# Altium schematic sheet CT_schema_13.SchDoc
size 387 x 385 mm
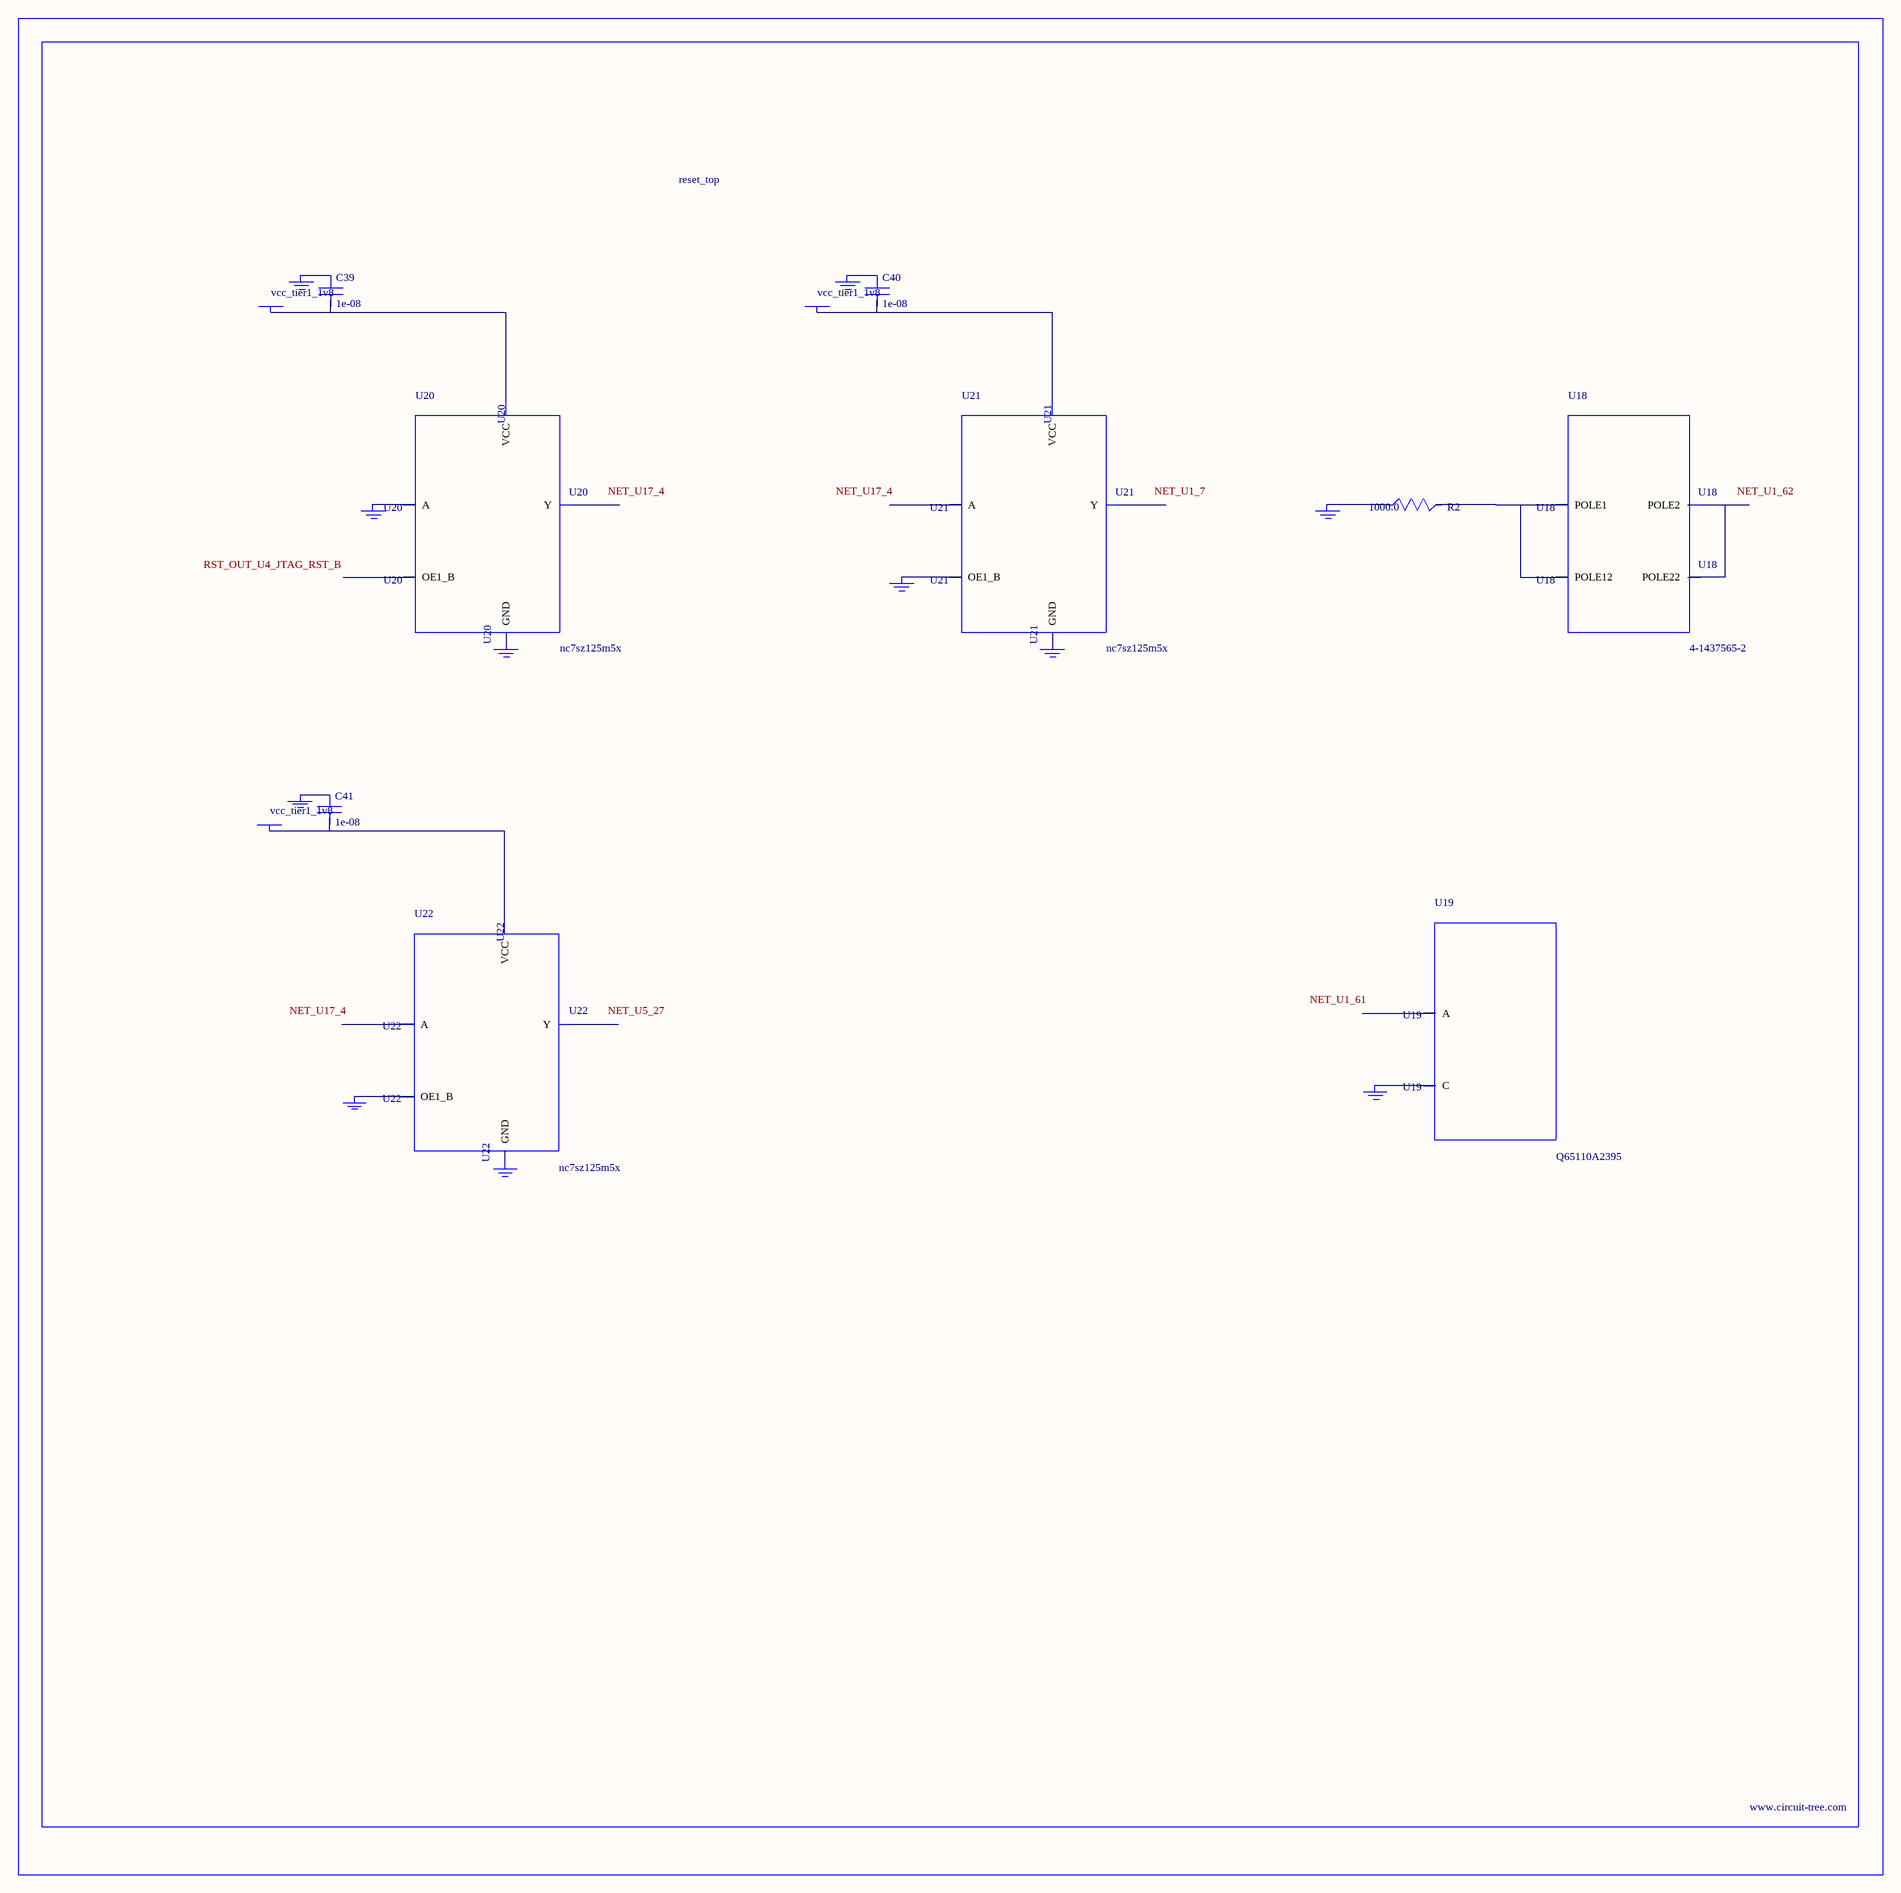
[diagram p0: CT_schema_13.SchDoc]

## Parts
BORDER12  (no value)
C39  1e-08  [C0402]
C40  1e-08  [C0402]
C41  1e-08  [C0402]
GND_INSTANCE_12_0  (no value)
GND_INSTANCE_12_1  (no value)
GND_INSTANCE_12_2  (no value)
GND_INSTANCE_12_3  (no value)
GND_INSTANCE_12_4  (no value)
GND_INSTANCE_12_5  (no value)
GND_INSTANCE_12_6  (no value)
GND_INSTANCE_12_7  (no value)
GND_INSTANCE_12_8  (no value)
GND_INSTANCE_12_9  (no value)
GND_INSTANCE_12_10  (no value)
POWER_INSTANCE_12_0  vcc_tier1_1v8
POWER_INSTANCE_12_1  vcc_tier1_1v8
POWER_INSTANCE_12_2  vcc_tier1_1v8
R2  1000.0  [R0603]
U18  4-1437565-2  [SW_4-1437565-2]
U19  Q65110A2395  [LGM67K-G1J2-24-Z]
U20  nc7sz125m5x  [NC7SZ125M5X]
U21  nc7sz125m5x  [NC7SZ125M5X]
U22  nc7sz125m5x  [NC7SZ125M5X]

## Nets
NetC39_1: C39.1 GND_INSTANCE_12_2.0(GND)
NetC39_2: C39.2 POWER_INSTANCE_12_0.0(PWR) U20.5(VCC)
NetC40_1: C40.1 GND_INSTANCE_12_5.0(GND)
NetC40_2: C40.2 POWER_INSTANCE_12_1.0(PWR) U21.5(VCC)
NetC41_1: C41.1 GND_INSTANCE_12_8.0(GND)
NetC41_2: C41.2 POWER_INSTANCE_12_2.0(PWR) U22.5(VCC)
NetGND_INSTANCE_12_0_0: GND_INSTANCE_12_0.0(GND) R2.1
NetGND_INSTANCE_12_1_0: GND_INSTANCE_12_1.0(GND) U19.C
NetGND_INSTANCE_12_3_0: GND_INSTANCE_12_3.0(GND) U20.2(A)
NetGND_INSTANCE_12_4_0: GND_INSTANCE_12_4.0(GND) U20.3(GND)
NetGND_INSTANCE_12_6_0: GND_INSTANCE_12_6.0(GND) U21.1(OE1_B)
NetGND_INSTANCE_12_7_0: GND_INSTANCE_12_7.0(GND) U21.3(GND)
NetGND_INSTANCE_12_9_0: GND_INSTANCE_12_9.0(GND) U22.1(OE1_B)
NetGND_INSTANCE_12_10_0: GND_INSTANCE_12_10.0(GND) U22.3(GND)
NetR2_2: R2.2 U18.1(POLE1) U18.2(POLE12)
NetU18_3: U18.3(POLE2) U18.4(POLE22)

Not connected (* = marked no-connect by the designer): U19 A; U20 1(OE1_B) 4(Y); U21 2(A) 4(Y); U22 2(A) 4(Y)

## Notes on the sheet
- Labels drawn without touching a wire or pin: NET_U1_7, NET_U1_61, NET_U1_62, NET_U5_27, NET_U17_4, RST_OUT_U4_JTAG_RST_B

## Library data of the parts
BORDER12 = BORDER_PAGE12
C39-C41 = C0402C103K3RAC
GND_INSTANCE_12_0-GND_INSTANCE_12_10 = GND
POWER_INSTANCE_12_0-POWER_INSTANCE_12_2 = PWR
R2 = RC0603JR-071KL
